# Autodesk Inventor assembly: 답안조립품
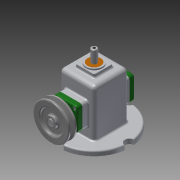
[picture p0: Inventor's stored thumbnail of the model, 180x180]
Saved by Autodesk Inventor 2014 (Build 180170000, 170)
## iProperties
Created: 2018-07
Part Number: 답안조립품
Document SubType Name: Assembly
Designer: kh
Author: kh
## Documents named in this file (17)
- C:\Users\kh\Desktop\480707V1019\답안조립품.iam
- 답안조립품.iam
- C:\Users\kh\Desktop\480707V1019\본체.ipt
- C:\Users\kh\Desktop\480707V1019\V벨트풀리.ipt
- C:\Users\kh\Desktop\480707V1019\고정핀 1.2x8.ipt
- C:\Users\kh\Desktop\480707V1019\뒤커버.ipt
- C:\Users\kh\Desktop\480707V1019\링크.ipt
- C:\Users\kh\Desktop\480707V1019\멈춤나사 M3x8.ipt
- C:\Users\kh\Desktop\480707V1019\베어링 12x32x10.ipt
- C:\Users\kh\Desktop\480707V1019\볼트 M4.ipt
- C:\Users\kh\Desktop\480707V1019\부시.ipt
- C:\Users\kh\Desktop\480707V1019\슬라이드.ipt
- C:\Users\kh\Desktop\480707V1019\앞커버.ipt
- C:\Users\kh\Desktop\480707V1019\오일 실 12 25 7.ipt
- C:\Users\kh\Desktop\480707V1019\키 4x4x10.ipt
- C:\Users\kh\Desktop\480707V1019\편심축.ipt
- C:\Users\kh\Desktop\480707V1019\핀 5x18.ipt
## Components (3 placed, 3 different names)
1. V벨트풀리:1 — Insert:13, Mate:3
2. 고정핀 1.2x8:1 — Mate:5, Mate:6
3. 핀 5x18:1 — Insert:9, Mate:5, Mate:6
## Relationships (5: Mate 3, Insert 2)
- Insert:9: 핀 5x18:1
- Insert:13: V벨트풀리:1
- Mate:3: V벨트풀리:1
- Mate:5: 고정핀 1.2x8:1 ↔ 핀 5x18:1
- Mate:6: 고정핀 1.2x8:1 ↔ 핀 5x18:1
